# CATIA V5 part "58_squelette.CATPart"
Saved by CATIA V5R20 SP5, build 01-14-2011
Part number: 58_squelette
Publications: "Plan yz", "Point.1", "Plan.1"
Bounding box of the stored display mesh (mm): x 0 to 0, y 147.862 to 147.862, z 111 to 111
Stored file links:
  C:\Documents and Settings\anizard\Bureau\13\58_squelette.CATPart
  C:\Documents and Settings\anizard\Bureau\13\anizard.CATProduct
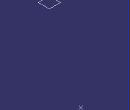
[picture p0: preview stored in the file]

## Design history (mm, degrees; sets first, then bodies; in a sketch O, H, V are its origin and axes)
Set1
  Point1: linked copy from another document
  Plane1: linked copy from another document
Body1 (main body)
  Point2: (0, 7.5, 0), relative to Point1
  Plane2: type Offset, RefPlane Plane1, Offset 18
